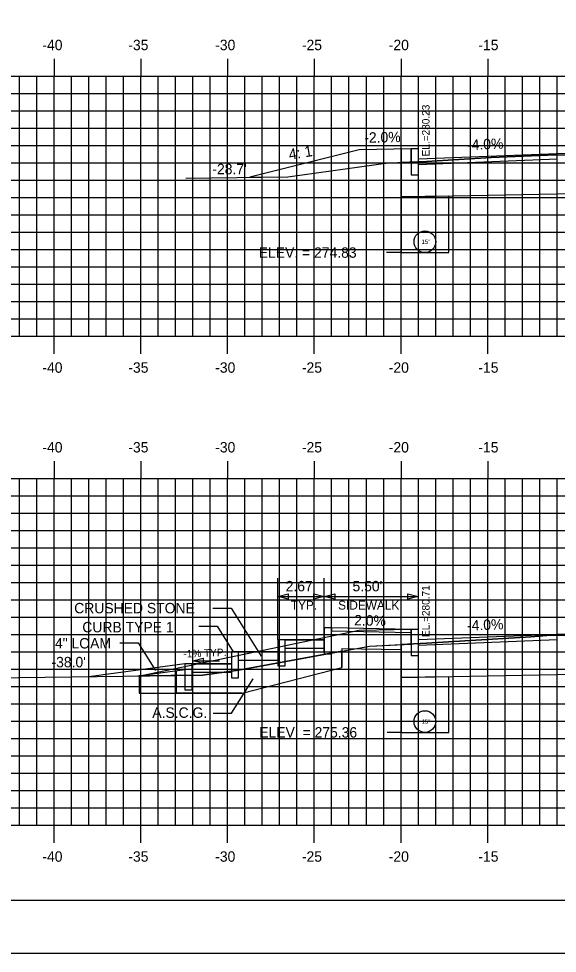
# Model space of a CAD drawing. Extents: x 853340 to 853510, y 366268 to 366378.
# Drawn here: x 853381.1 to 853412.1, y 366268.2 to 366322.1 of the extents above; entities that cross this region are included whole.
import ezdxf

# ---------------------------------------------------------------- set-up
doc = ezdxf.new("R2010")
doc.units = 0
for name, color, linetype in [('ANNOTATION', 7, 'Continuous'), ('BORDER', 7, 'Continuous'), ('D_Curb_Type_1_Lt', 7, 'Continuous'), ('D_Roadway_Edge_TW', 7, 'Continuous'), ('D_Roadway_FinishedGrade', 7, 'Continuous'), ('D_Roadway_Sidewalks_Paved', 7, 'Continuous'), ('D_Roadway_SubGrade', 7, 'Continuous'), ('D_Text_Standard', 7, 'Continuous'), ('DIMENSIONS', 7, 'Continuous'), ('H_V ANNOTATION', 7, 'Continuous'), ('JUNK COM EXC', 7, 'Continuous'), ('JUNK FILL', 7, 'Continuous'), ('junk strct exc', 7, 'Continuous'), ('MAJOR', 7, 'Continuous'), ('MINOR', 7, 'Continuous'), ('PATTERNING', 7, 'Continuous'), ('PDRAIN', 7, 'Continuous'), ('PLOT BOUNDARY', 7, 'Continuous'), ('S_Roadway_Centerline', 7, 'Continuous')]:
    doc.layers.add(name, color=color, linetype=linetype)

msp = doc.modelspace()

# ---------------------------------------------------------------- linework, layer by layer
at = {"layer": 'ANNOTATION'}
for points in [[(853392.258, 366288.071), (853393.31, 366288.071), (853395.042, 366285.32)], [(853391.446, 366287.035), (853392.498, 366287.035), (853393.428, 366285.559)], [(853386.889, 366286.09), (853387.94, 366286.09), (853388.954, 366284.482)], [(853392.28, 366282.035), (853393.332, 366282.035), (853394.578, 366284.013)]]:
    msp.add_lwpolyline(points, dxfattribs=at)
at = {"layer": 'BORDER'}
msp.add_line((853348.1, 366271.236), (853508.1, 366271.236), dxfattribs=at)
at = {"layer": 'D_Curb_Type_1_Lt'}
for points in [[(853403.683, 366314.568), (853403.683, 366313.068), (853404.1, 366313.068), (853404.1, 366314.568)], [(853398.678, 366286.941), (853398.678, 366285.441), (853399.095, 366285.441), (853399.095, 366286.941)], [(853403.683, 366286.85), (853403.683, 366285.35), (853404.1, 366285.35), (853404.1, 366286.85)], [(853395.998, 366286.249), (853395.998, 366284.749), (853396.415, 366284.749), (853396.415, 366286.249)], [(853393.318, 366285.556), (853393.318, 366284.056), (853393.735, 366284.056), (853393.735, 366285.556)], [(853390.638, 366284.864), (853390.638, 366283.364), (853391.055, 366283.364), (853391.055, 366284.864)]]:
    msp.add_lwpolyline(points, close=True, dxfattribs=at)
at = {"layer": 'D_Roadway_Edge_TW'}
for p, q in [((853404.1, 366313.985), (853412.1, 366314.305)), ((853412.1, 366314.305), (853423.1, 366314.419))]:
    msp.add_line(p, q, dxfattribs=at)
msp.add_lwpolyline([(853404.1, 366286.267), (853412.1, 366286.587), (853423.1, 366286.701), (853434.1, 366286.48), (853442.1, 366286.16)], dxfattribs=at)
at = {"layer": 'D_Roadway_FinishedGrade'}
for p, q in [((853400.683, 366314.508), (853394.382, 366312.933)), ((853390.638, 366284.864), (853385.1, 366284.13))]:
    msp.add_line(p, q, dxfattribs=at)
msp.add_lwpolyline([(853403.683, 366314.568), (853400.683, 366314.508)], dxfattribs=at)
at = {"layer": 'D_Roadway_Sidewalks_Paved'}
for p, q in [((853398.678, 366286.249), (853395.998, 366286.249)), ((853395.998, 366285.556), (853393.318, 366285.556)), ((853398.678, 366285.749), (853396.415, 366285.749)), ((853395.998, 366285.056), (853393.735, 366285.056)), ((853393.318, 366284.864), (853390.638, 366284.864)), ((853393.318, 366284.364), (853391.055, 366284.364))]:
    msp.add_line(p, q, dxfattribs=at)
msp.add_lwpolyline([(853403.683, 366286.85), (853399.095, 366286.941), (853399.095, 366286.775), (853403.683, 366286.683)], close=True, dxfattribs=at)
at = {"layer": 'D_Roadway_SubGrade'}
for p, q in [((853399.678, 366285.764), (853399.678, 366284.652)), ((853390.638, 366284.528), (853387.922, 366284.168)), ((853390.138, 366284.461), (853390.138, 366283.171)), ((853393.945, 366283.171), (853399.678, 366284.652)), ((853393.945, 366283.171), (853390.138, 366283.171))]:
    msp.add_line(p, q, dxfattribs=at)
for points in [[(853403.1, 366314.557), (853403.1, 366311.792)], [(853403.1, 366311.792), (853412.108, 366311.972), (853412.108, 366313.972), (853404.1, 366313.652)], [(853403.1, 366284.074), (853412.108, 366284.254), (853412.108, 366286.254), (853404.1, 366285.933)], [(853399.678, 366285.764), (853403.1, 366285.695), (853403.1, 366284.074)], [(853403.1, 366285.695), (853403.1, 366284.074)]]:
    msp.add_lwpolyline(points, dxfattribs=at)
at = {"layer": 'D_Text_Standard'}
for points in [[(853403.1, 366308.587), (853402.939, 366308.587), (853402.259, 366308.587)], [(853403.1, 366280.919), (853402.974, 366280.919), (853402.294, 366280.919)]]:
    msp.add_lwpolyline(points, dxfattribs=at)
at = {"layer": 'DIMENSIONS'}
for p, q in [((853395.998, 366286.249), (853395.998, 366289.814)), ((853398.678, 366285.504), (853398.678, 366289.814)), ((853404.1, 366286.85), (853404.1, 366289.814)), ((853395.998, 366288.751), (853398.678, 366288.751)), ((853398.678, 366288.751), (853404.096, 366288.751)), ((853391.101, 366285.049), (853392.645, 366285.049))]:
    msp.add_line(p, q, dxfattribs=at)
for points in [[(853396.598, 366288.601), (853395.998, 366288.751), (853396.598, 366288.901)], [(853398.078, 366288.901), (853398.678, 366288.751), (853398.078, 366288.601)], [(853399.278, 366288.601), (853398.678, 366288.751), (853399.278, 366288.901)], [(853403.496, 366288.901), (853404.096, 366288.751), (853403.496, 366288.601)], [(853391.701, 366284.899), (853391.101, 366285.049), (853391.701, 366285.199)]]:
    msp.add_lwpolyline(points, close=True, dxfattribs=at)
at = {"layer": 'JUNK COM EXC'}
for points in [[(853403.1, 366313.783), (853403.1, 366311.792), (853412.108, 366311.972), (853423.108, 366312.03), (853443.1, 366311.63), (853443.1, 366313.251), (853447.105, 366313.332), (853447.105, 366313.648), (853444.01, 366313.735), (853443.885, 366313.73), (853441.643, 366313.789), (853435.938, 366313.988), (853425.848, 366314.256), (853423.1, 366314.352), (853417.701, 366314.327), (853411.542, 366314.212), (853408.292, 366314.075), (853404.573, 366313.84), (853403.1, 366313.783)], [(853403.1, 366285.982), (853403.1, 366284.074), (853412.108, 366284.254), (853423.108, 366284.368), (853443.1, 366283.968), (853443.1, 366285.588), (853447.105, 366285.669), (853447.105, 366286.025), (853442.522, 366286.163), (853440.609, 366286.208), (853435.982, 366286.375), (853424.096, 366286.691), (853423.104, 366286.714), (853422.159, 366286.693), (853411.503, 366286.496), (853410.582, 366286.432), (853404.575, 366286.053), (853403.1, 366285.982)], [(853399.678, 366285.599), (853393.728, 366284.501), (853391.663, 366284.218), (853388.007, 366284.169), (853388.007, 366283.171), (853393.945, 366283.171), (853399.678, 366284.652), (853399.678, 366285.599)]]:
    msp.add_lwpolyline(points, dxfattribs=at)
at = {"layer": 'JUNK FILL'}
for points in [[(853403.683, 366313.805), (853403.683, 366314.568), (853400.683, 366314.508), (853394.382, 366312.933), (853396.582, 366312.962), (853402.362, 366313.754)], [(853403.683, 366286.01), (853403.683, 366286.85), (853400.683, 366286.79), (853388.13, 366284.171), (853391.663, 366284.218), (853393.728, 366284.501), (853401.276, 366285.894)]]:
    msp.add_lwpolyline(points, close=True, dxfattribs=at)
at = {"layer": 'junk strct exc'}
for points in [[(853403.1, 366311.792), (853403.1, 366308.587), (853405.85, 366308.587), (853405.85, 366311.847)], [(853403.1, 366284.074), (853403.1, 366280.919), (853405.85, 366280.919), (853405.85, 366284.129)]]:
    msp.add_lwpolyline(points, close=True, dxfattribs=at)
at = {"layer": 'MAJOR'}
for p, q in [((853383.1, 366319.759), (853383.1, 366318.757)), ((853388.1, 366319.759), (853388.1, 366318.757)), ((853393.1, 366319.759), (853393.1, 366318.757)), ((853398.1, 366319.759), (853398.1, 366318.757)), ((853403.1, 366319.759), (853403.1, 366318.757)), ((853408.1, 366319.759), (853408.1, 366318.757)), ((853353.1, 366318.757), (853493.1, 366318.757)), ((853353.1, 366318.757), (853493.1, 366318.757)), ((853383.1, 366303.757), (853383.1, 366318.757)), ((853388.1, 366303.757), (853388.1, 366318.757)), ((853393.1, 366303.757), (853393.1, 366318.757)), ((853398.1, 366303.757), (853398.1, 366318.757)), ((853403.1, 366303.757), (853403.1, 366318.757)), ((853408.1, 366303.757), (853408.1, 366318.757)), ((853353.1, 366313.757), (853493.1, 366313.757)), ((853353.1, 366308.757), (853493.1, 366308.757)), ((853353.1, 366303.757), (853493.1, 366303.757)), ((853383.1, 366302.755), (853383.1, 366303.757)), ((853388.1, 366302.755), (853388.1, 366303.757)), ((853393.1, 366302.755), (853393.1, 366303.757)), ((853398.1, 366302.755), (853398.1, 366303.757)), ((853403.1, 366302.755), (853403.1, 366303.757)), ((853408.1, 366302.755), (853408.1, 366303.757)), ((853383.1, 366296.561), (853383.1, 366295.559)), ((853388.1, 366296.561), (853388.1, 366295.559)), ((853393.1, 366296.561), (853393.1, 366295.559)), ((853398.1, 366296.561), (853398.1, 366295.559)), ((853403.1, 366296.561), (853403.1, 366295.559)), ((853408.1, 366296.561), (853408.1, 366295.559)), ((853353.1, 366295.559), (853493.1, 366295.559)), ((853353.1, 366295.559), (853493.1, 366295.559)), ((853383.1, 366275.559), (853383.1, 366295.559)), ((853388.1, 366275.559), (853388.1, 366295.559)), ((853393.1, 366275.559), (853393.1, 366295.559)), ((853398.1, 366275.559), (853398.1, 366295.559)), ((853403.1, 366275.559), (853403.1, 366295.559)), ((853408.1, 366275.559), (853408.1, 366295.559)), ((853353.1, 366290.559), (853493.1, 366290.559)), ((853353.1, 366285.559), (853493.1, 366285.559)), ((853353.1, 366280.559), (853493.1, 366280.559)), ((853353.1, 366275.559), (853493.1, 366275.559)), ((853353.1, 366275.559), (853493.1, 366275.559)), ((853383.1, 366274.557), (853383.1, 366275.559)), ((853388.1, 366274.557), (853388.1, 366275.559)), ((853393.1, 366274.557), (853393.1, 366275.559)), ((853398.1, 366274.557), (853398.1, 366275.559)), ((853403.1, 366274.557), (853403.1, 366275.559)), ((853408.1, 366274.557), (853408.1, 366275.559))]:
    msp.add_line(p, q, dxfattribs=at)
at = {"layer": 'MINOR'}
for p, q in [((853381.1, 366303.757), (853381.1, 366318.757)), ((853382.1, 366303.757), (853382.1, 366318.757)), ((853384.1, 366303.757), (853384.1, 366318.757)), ((853385.1, 366303.757), (853385.1, 366318.757)), ((853386.1, 366303.757), (853386.1, 366318.757)), ((853387.1, 366303.757), (853387.1, 366318.757)), ((853389.1, 366303.757), (853389.1, 366318.757)), ((853390.1, 366303.757), (853390.1, 366318.757)), ((853391.1, 366303.757), (853391.1, 366318.757)), ((853392.1, 366303.757), (853392.1, 366318.757)), ((853394.1, 366303.757), (853394.1, 366318.757)), ((853395.1, 366303.757), (853395.1, 366318.757)), ((853396.1, 366303.757), (853396.1, 366318.757)), ((853397.1, 366303.757), (853397.1, 366318.757)), ((853399.1, 366303.757), (853399.1, 366318.757)), ((853400.1, 366303.757), (853400.1, 366318.757)), ((853401.1, 366303.757), (853401.1, 366318.757)), ((853402.1, 366303.757), (853402.1, 366318.757)), ((853404.1, 366303.757), (853404.1, 366318.757)), ((853405.1, 366303.757), (853405.1, 366318.757)), ((853406.1, 366303.757), (853406.1, 366318.757)), ((853407.1, 366303.757), (853407.1, 366318.757)), ((853409.1, 366303.757), (853409.1, 366318.757)), ((853410.1, 366303.757), (853410.1, 366318.757)), ((853411.1, 366303.757), (853411.1, 366318.757)), ((853412.1, 366303.757), (853412.1, 366318.757)), ((853353.1, 366317.757), (853493.1, 366317.757)), ((853353.1, 366316.757), (853493.1, 366316.757)), ((853353.1, 366315.757), (853493.1, 366315.757)), ((853353.1, 366314.757), (853493.1, 366314.757)), ((853353.1, 366312.757), (853493.1, 366312.757)), ((853353.1, 366311.757), (853493.1, 366311.757)), ((853353.1, 366310.757), (853493.1, 366310.757)), ((853353.1, 366309.757), (853493.1, 366309.757)), ((853353.1, 366307.757), (853493.1, 366307.757)), ((853353.1, 366306.757), (853493.1, 366306.757)), ((853353.1, 366305.757), (853493.1, 366305.757)), ((853353.1, 366304.757), (853493.1, 366304.757)), ((853381.1, 366275.559), (853381.1, 366295.559)), ((853382.1, 366275.559), (853382.1, 366295.559)), ((853384.1, 366275.559), (853384.1, 366295.559)), ((853385.1, 366275.559), (853385.1, 366295.559)), ((853386.1, 366275.559), (853386.1, 366295.559)), ((853387.1, 366275.559), (853387.1, 366295.559)), ((853389.1, 366275.559), (853389.1, 366295.559)), ((853390.1, 366275.559), (853390.1, 366295.559)), ((853391.1, 366275.559), (853391.1, 366295.559)), ((853392.1, 366275.559), (853392.1, 366295.559)), ((853394.1, 366275.559), (853394.1, 366295.559)), ((853395.1, 366275.559), (853395.1, 366295.559)), ((853396.1, 366275.559), (853396.1, 366295.559)), ((853397.1, 366275.559), (853397.1, 366295.559)), ((853399.1, 366275.559), (853399.1, 366295.559)), ((853400.1, 366275.559), (853400.1, 366295.559)), ((853401.1, 366275.559), (853401.1, 366295.559)), ((853402.1, 366275.559), (853402.1, 366295.559)), ((853404.1, 366275.559), (853404.1, 366295.559)), ((853405.1, 366275.559), (853405.1, 366295.559)), ((853406.1, 366275.559), (853406.1, 366295.559)), ((853407.1, 366275.559), (853407.1, 366295.559)), ((853409.1, 366275.559), (853409.1, 366295.559)), ((853410.1, 366275.559), (853410.1, 366295.559)), ((853411.1, 366275.559), (853411.1, 366295.559)), ((853412.1, 366275.559), (853412.1, 366295.559)), ((853353.1, 366294.559), (853493.1, 366294.559)), ((853353.1, 366293.559), (853493.1, 366293.559)), ((853353.1, 366292.559), (853493.1, 366292.559)), ((853353.1, 366291.559), (853493.1, 366291.559)), ((853353.1, 366289.559), (853493.1, 366289.559)), ((853353.1, 366288.559), (853493.1, 366288.559)), ((853353.1, 366287.559), (853493.1, 366287.559)), ((853353.1, 366286.559), (853493.1, 366286.559)), ((853353.1, 366284.559), (853493.1, 366284.559)), ((853353.1, 366283.559), (853493.1, 366283.559)), ((853353.1, 366282.559), (853493.1, 366282.559)), ((853353.1, 366281.559), (853493.1, 366281.559)), ((853353.1, 366279.559), (853493.1, 366279.559)), ((853353.1, 366278.559), (853493.1, 366278.559)), ((853353.1, 366277.559), (853493.1, 366277.559)), ((853353.1, 366276.559), (853493.1, 366276.559))]:
    msp.add_line(p, q, dxfattribs=at)
at = {"layer": 'PATTERNING'}
for points in [[(853396.415, 366286.249), (853398.678, 366286.249), (853398.678, 366285.749), (853396.415, 366285.749), (853396.415, 366286.249)], [(853393.735, 366285.556), (853395.998, 366285.556), (853395.998, 366285.056), (853393.735, 366285.056), (853393.735, 366285.556)], [(853391.055, 366284.864), (853393.318, 366284.864), (853393.318, 366284.364), (853391.055, 366284.364), (853391.055, 366284.864)]]:
    msp.add_lwpolyline(points, close=True, dxfattribs=at)
at = {"layer": 'PDRAIN'}
for points in [[(853403.1, 366311.792), (853403.1, 366308.587), (853405.85, 366308.587), (853405.85, 366311.847)], [(853403.1, 366284.074), (853403.1, 366280.919), (853405.85, 366280.919), (853405.85, 366284.129)]]:
    msp.add_lwpolyline(points, dxfattribs=at)
for centre in [(853404.475, 366309.212), (853404.475, 366281.544)]:
    msp.add_circle(centre, 0.625, dxfattribs=at)
at = {"layer": 'PLOT BOUNDARY'}
msp.add_lwpolyline([(853340.007, 366268.177), (853510.007, 366268.177), (853510.007, 366378.177), (853340.007, 366378.177)], close=True, dxfattribs=at)
at = {"layer": 'S_Roadway_Centerline'}
for points in [[(853390.695, 366312.884), (853396.582, 366312.962), (853402.362, 366313.754), (853404.573, 366313.84), (853408.292, 366314.075), (853411.542, 366314.212), (853417.701, 366314.327), (853423.1, 366314.352), (853425.848, 366314.256), (853435.938, 366313.988), (853441.643, 366313.789), (853443.885, 366313.73), (853444.01, 366313.735), (853448.826, 366313.6), (853449.069, 366313.813), (853449.359, 366313.991), (853449.683, 366313.823), (853449.767, 366313.833), (853452.013, 366313.927), (853454.293, 366314.022), (853454.426, 366314.05), (853454.571, 366314.069)], [(853378.002, 366284.035), (853391.663, 366284.218), (853393.728, 366284.501), (853401.276, 366285.894), (853404.575, 366286.053), (853410.582, 366286.432), (853411.503, 366286.496), (853422.159, 366286.693), (853423.104, 366286.714), (853424.096, 366286.691), (853435.982, 366286.375), (853440.609, 366286.208), (853442.522, 366286.163), (853448.883, 366285.971), (853449.042, 366286.069), (853449.557, 366286.324), (853451.29, 366286.654), (853460.175, 366287.602), (853462.142, 366287.892)]]:
    msp.add_lwpolyline(points, dxfattribs=at)

# ---------------------------------------------------------------- texts
at = {"layer": 'ANNOTATION'}
for s, height, rotation, p in [('-2.0%', 0.6, 1.1458, (853400.986, 366314.915)), ('-4.0%', 0.6, 2.2906, (853406.916, 366314.498)), ('4: 1', 0.6188, 9.4623, (853396.676, 366313.932)), ('2.0%', 0.6, 358.8637, (853400.394, 366287.089)), ('-4.0%', 0.6, 2.2906, (853406.916, 366286.78)), ('-1% TYP.', 0.4335, 2.2906, (853390.56, 366285.226))]:
    msp.add_text(s, height=height, rotation=rotation, dxfattribs=at).set_placement(p)
for s, p in [('CRUSHED STONE', (853384.261, 366287.783)), ('CURB TYPE 1', (853384.728, 366286.685)), ('4" LOAM', (853383.152, 366285.755)), ('A.S.C.G.', (853388.762, 366281.756))]:
    msp.add_text(s, height=0.6, dxfattribs=at).set_placement(p)
at = {"layer": 'D_Text_Standard'}
for s, p in [(' EL.=280.23', (853404.743, 366313.973)), (' EL.=280.71', (853404.743, 366286.255))]:
    msp.add_text(s, height=0.4335, rotation=90, dxfattribs=at).set_placement(p)
for s, p in [("-28.7'", (853392.223, 366313.104)), ('ELEV. = 274.83', (853394.896, 366308.287)), ("-38.0'", (853382.951, 366284.671)), ('ELEV. = 275.36', (853394.926, 366280.619))]:
    msp.add_text(s, height=0.6, dxfattribs=at).set_placement(p)
at = {"layer": 'DIMENSIONS'}
for s, height, p in [("2.67'", 0.6, (853396.451, 366289.051)), ("5.50'", 0.6, (853400.303, 366289.051)), ('TYP.', 0.51, (853396.746, 366287.998)), ('SIDEWALK', 0.51, (853399.475, 366287.998))]:
    msp.add_text(s, height=height, dxfattribs=at).set_placement(p)
at = {"layer": 'H_V ANNOTATION'}
for s, p in [('-40', (853382.425, 366320.257)), ('-35', (853387.38, 366320.257)), ('-30', (853392.388, 366320.257)), ('-25', (853397.385, 366320.257)), ('-20', (853402.393, 366320.257)), ('-15', (853407.557, 366320.257)), ('-40', (853382.425, 366301.657)), ('-35', (853387.38, 366301.657)), ('-30', (853392.388, 366301.657)), ('-25', (853397.385, 366301.657)), ('-20', (853402.393, 366301.657)), ('-15', (853407.557, 366301.657)), ('-40', (853382.425, 366297.059)), ('-35', (853387.38, 366297.059)), ('-30', (853392.388, 366297.059)), ('-25', (853397.385, 366297.059)), ('-20', (853402.393, 366297.059)), ('-15', (853407.557, 366297.059)), ('-40', (853382.425, 366273.459)), ('-35', (853387.38, 366273.459)), ('-30', (853392.388, 366273.459)), ('-25', (853397.385, 366273.459)), ('-20', (853402.393, 366273.459)), ('-15', (853407.557, 366273.459))]:
    msp.add_text(s, height=0.6, dxfattribs=at).set_placement(p)
at = {"layer": 'PDRAIN'}
for p in [(853404.288, 366309.087), (853404.288, 366281.419)]:
    msp.add_text('15"', height=0.25, dxfattribs=at).set_placement(p)

doc.saveas('drawing.dxf')
